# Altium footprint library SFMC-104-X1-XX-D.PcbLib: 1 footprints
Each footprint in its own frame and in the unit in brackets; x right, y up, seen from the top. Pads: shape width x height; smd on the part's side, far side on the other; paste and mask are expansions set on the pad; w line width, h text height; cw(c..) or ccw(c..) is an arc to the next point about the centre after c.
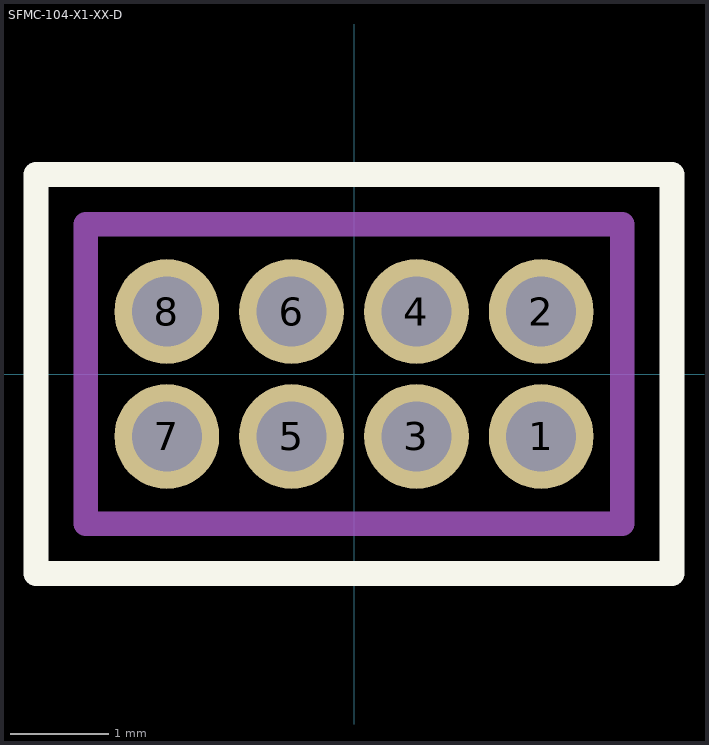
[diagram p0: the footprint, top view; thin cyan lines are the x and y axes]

## SFMC-104-X1-XX-D [mil]
pads (8):
  round 42 hole 28 mask+3: 1(75,-25) 2(75,25) 3(25,-25) 4(25,25) 5(-25,-25) 6(-25,25) 7(-75,-25) 8(-75,25)
Top Overlay:
  lines w10: -127.5,-80 -127.5,80 127.5,80 127.5,-80 -127.5,-80
Mechanical 1:
  lines w10: -107.5,-60 -107.5,60 107.5,60 107.5,-60 -107.5,-60
  text "J1" at -27.57,-128 h30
